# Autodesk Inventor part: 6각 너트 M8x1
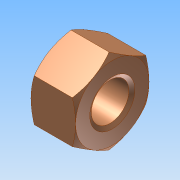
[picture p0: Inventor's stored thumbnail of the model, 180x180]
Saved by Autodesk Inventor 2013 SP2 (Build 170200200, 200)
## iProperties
Created: 2025-10
Part Number: 6각 너트 M8x1
Material: Generic
Document SubType Name: Modeling
Designer: a
Density: 1 g/cm^3
Author: a
변환 표준: STEP AP214IS
전처리기: Build: 200, Release: 2013 SP2 Update 6 - Date: Thu 07/17/2014
전송 단위: 밀리미터
불확실성: 0.01
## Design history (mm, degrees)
node "6각 너트 M8x11"
body "Solid1"
node "기준1"
